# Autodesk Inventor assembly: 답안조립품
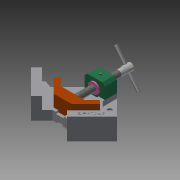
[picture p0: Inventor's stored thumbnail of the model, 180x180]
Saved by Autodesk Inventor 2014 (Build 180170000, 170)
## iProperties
Created: 2019-04
Part Number: 답안조립품
Document SubType Name: Assembly
Designer: kh
Author: kh
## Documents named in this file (11)
- C:\Users\kh\Desktop\490407V1022\답안조립품.iam
- C:\Users\kh\Desktop\490407V1022\본체.ipt
- C:\Users\kh\Desktop\490407V1022\리드스크류.ipt
- C:\Users\kh\Desktop\490407V1022\멈춤나사 M4x5.ipt
- C:\Users\kh\Desktop\490407V1022\멈춤나사 M4x10.ipt
- C:\Users\kh\Desktop\490407V1022\볼트 M4x16.ipt
- C:\Users\kh\Desktop\490407V1022\부시.ipt
- C:\Users\kh\Desktop\490407V1022\서포트.ipt
- C:\Users\kh\Desktop\490407V1022\조.ipt
- C:\Users\kh\Desktop\490407V1022\평행 핀 2.5x24.ipt
- C:\Users\kh\Desktop\490407V1022\핸들.ipt
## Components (1 placed, 1 different names)
1. 핸들:1 — Mate:5, Mate:6, Mate:7, Mate:15, Mate:16, Mate:17
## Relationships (6: Mate 6)
- Mate:5: 핸들:1
- Mate:6: 핸들:1
- Mate:7: 핸들:1
- Mate:15: 핸들:1
- Mate:16: 핸들:1
- Mate:17: 핸들:1
